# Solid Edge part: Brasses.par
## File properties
Author: Sarvanan
Template: Sync Iso Part.par
Last saved by: Sham
Revision: 13
Application: Solid Edge
Accuracy: 0.990
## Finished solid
Body 1: solid body, 16 faces, 18 edges, 0 vertices.
  Faces by surface: cylinder 9, plane 7
  Edges by curve: circle 14, intersection 4
Bounding box of the edges (mm): 64.000 x 64.000 x 64.000, from (-32.001, -32, -32) to (31.999, 32, 32).
Cylindrical faces by radius (mm): R3 x2, R4 x1, R16 x1, R22 x1, R24 x2, R32 x2
Planar faces by outward normal: +x 3, +z 1, -x 3
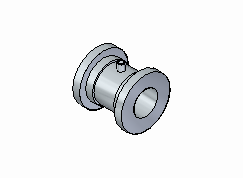
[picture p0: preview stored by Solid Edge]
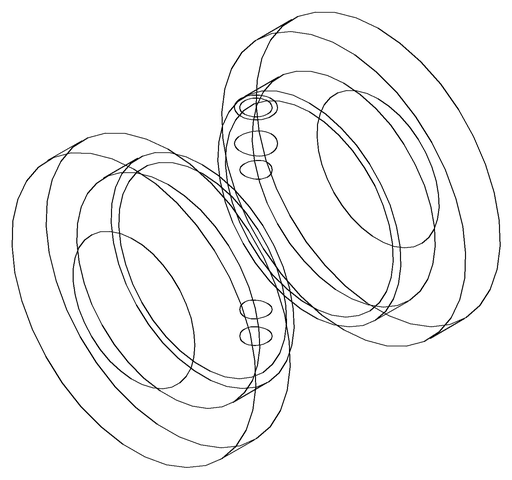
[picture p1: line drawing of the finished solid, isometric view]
